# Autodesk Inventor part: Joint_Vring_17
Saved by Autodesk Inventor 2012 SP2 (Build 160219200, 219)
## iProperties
Created: 2013-04
Part Number: Joint_Vring_17
Material: Default
Document SubType Name: Modeling
Designer: papa
Density: 1 g/cm^3
Mass: 0.810151 g
Surface Area: 12.5756 cm^2
Volume: 0.810151 cm^3
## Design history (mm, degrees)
node "Joint_Vring_171"
node "Joint_Vring_17"
node "Base1"
